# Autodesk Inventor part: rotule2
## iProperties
Created: 2002-09
Part Number: rotule2
Material: Par défaut
Document SubType Name: Modélisation
Designer: Maison
Control State: 0
Master: False
Checked Out: False
Shininess: 20.0
Length Units: 11269
Angle Units: 11279
Time Units: 11290
Mass Units: 11283
Length Display Precision: 3
Angle Display Precision: 2
Density: 0.0
Volumn: 0.0
Area: 0.0
PropertySet Name: Model Information
Author: Maison
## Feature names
1. Révolution1 [Revolution]
2. Perçage1 [Hole]
